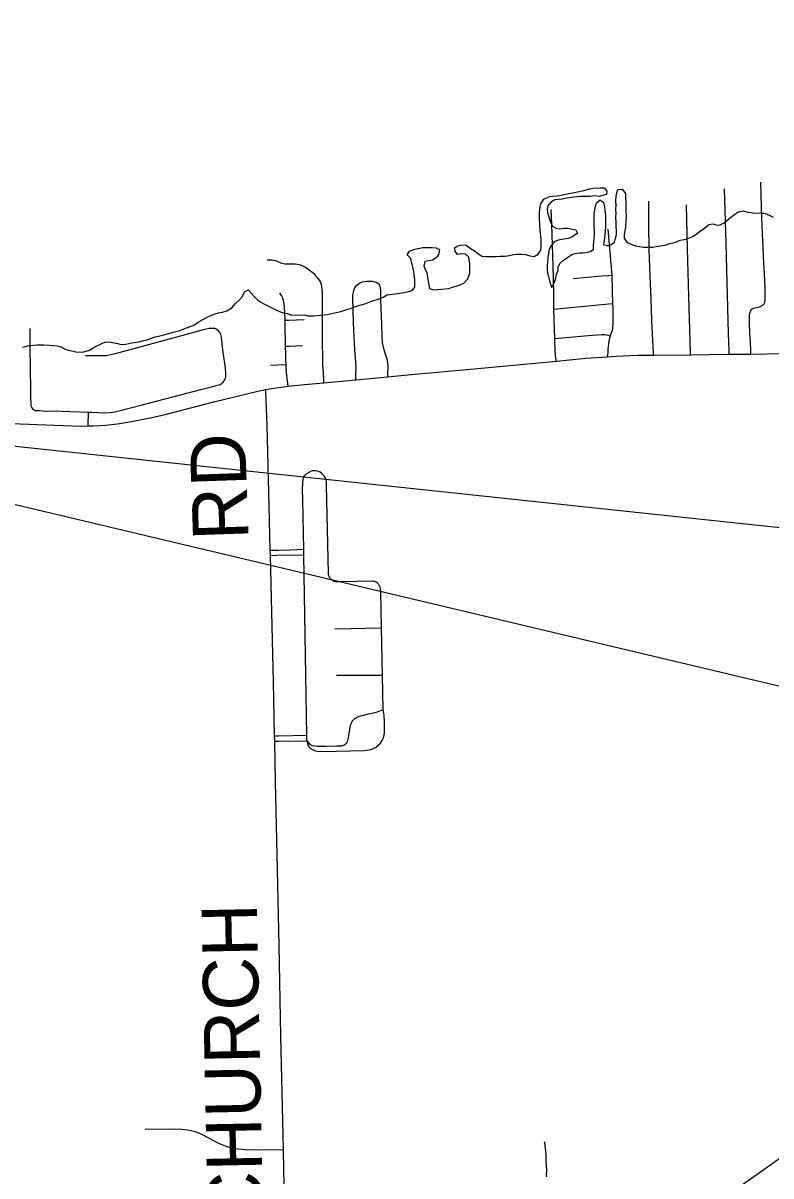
# Model space of a CAD drawing. Extents: x 63.4 to 97.4, y 0.4 to 22.4.
# Drawn here: x 69.962 to 70.728, y 16.848 to 18.029 of the extents above; entities that cross this region are included whole.
import ezdxf

# ---------------------------------------------------------------- set-up
doc = ezdxf.new("R2010")
doc.units = 0
for name, color, linetype in [('GM_X_County_Road', 7, 'Continuous'), ('GM_X_County_Road_Text', 7, 'Continuous'), ('GM_X_Minor_River', 7, 'Continuous'), ('GM_X_Rail_Line', 7, 'Continuous'), ('GM_X_State_Route', 7, 'Continuous'), ('GM_X_Township_Road', 7, 'Continuous'), ('SH_Data', 7, 'Continuous')]:
    doc.layers.add(name, color=color, linetype=linetype)

msp = doc.modelspace()

# ---------------------------------------------------------------- linework, layer by layer
at = {"layer": 'GM_X_County_Road'}
msp.add_line((70.2206, 17.2519), (70.2198, 17.2935), dxfattribs=at)
for points in [[(70.2154, 17.4839), (70.2152, 17.4891), (70.2142, 17.5343), (70.212, 17.6174), (70.2112, 17.643), (70.2106, 17.6524), (70.2104, 17.6537)], [(70.2198, 17.2935), (70.2198, 17.2953), (70.2197, 17.299), (70.2185, 17.3543), (70.2168, 17.4257), (70.2154, 17.4839)], [(70.2287, 16.8754), (70.2281, 16.9044), (70.2262, 16.9913), (70.2244, 17.0843), (70.2232, 17.1308), (70.2222, 17.1774), (70.2206, 17.2519)], [(70.2316, 16.7501), (70.2293, 16.8544), (70.2287, 16.8754)]]:
    msp.add_lwpolyline(points, dxfattribs=at)
at = {"layer": 'GM_X_Minor_River'}
for points in [[(70.3259, 17.7464), (70.3308, 17.7483), (70.335, 17.7506), (70.3433, 17.7518), (70.3479, 17.7526), (70.352, 17.753), (70.357, 17.7542), (70.3604, 17.7553), (70.3634, 17.7587), (70.3634, 17.7656), (70.363, 17.769), (70.3622, 17.7747), (70.3598, 17.785), (70.3587, 17.7884), (70.3556, 17.7918), (70.3579, 17.7956), (70.3621, 17.7971), (70.3666, 17.7983), (70.3715, 17.7991), (70.381, 17.7991), (70.3852, 17.7988), (70.3886, 17.7973), (70.3879, 17.7931), (70.386, 17.7893), (70.3815, 17.7862), (70.3773, 17.7854), (70.3735, 17.785), (70.3724, 17.7805), (70.3739, 17.777), (70.3755, 17.7732), (70.3763, 17.7687), (70.3774, 17.7626), (70.3782, 17.7573), (70.3824, 17.7558), (70.3862, 17.7562), (70.3907, 17.7566), (70.3976, 17.7574), (70.4017, 17.7585), (70.4086, 17.7605), (70.4135, 17.7628), (70.4176, 17.767), (70.4195, 17.7731), (70.4195, 17.7826), (70.4187, 17.7894), (70.4152, 17.7924), (70.4111, 17.7928), (70.4069, 17.792), (70.4046, 17.7954), (70.4038, 17.7988), (70.4072, 17.8011), (70.4114, 17.8019), (70.4159, 17.8016), (70.4198, 17.7985), (70.4255, 17.7951), (70.4289, 17.7925), (70.4323, 17.7902), (70.4365, 17.7899), (70.4468, 17.7899), (70.4506, 17.7903), (70.4555, 17.7903), (70.4604, 17.7911), (70.4642, 17.7919), (70.4676, 17.7923), (70.4733, 17.7923), (70.4767, 17.792), (70.4809, 17.7908), (70.4855, 17.7901), (70.4896, 17.7924), (70.4923, 17.7966), (70.4926, 17.8019), (70.4926, 17.8072), (70.4922, 17.811), (70.4918, 17.8164), (70.4914, 17.8224), (70.491, 17.83), (70.491, 17.8342), (70.4913, 17.8388), (70.4924, 17.8441), (70.4954, 17.8487), (70.5011, 17.8514), (70.5049, 17.8518), (70.5117, 17.8526), (70.5208, 17.8545), (70.5246, 17.8553), (70.5299, 17.8561), (70.5364, 17.8576), (70.5425, 17.8592), (70.5459, 17.8599), (70.5531, 17.8604), (70.5573, 17.8604), (70.5599, 17.857), (70.5596, 17.8535), (70.5516, 17.8516), (70.5474, 17.852), (70.5433, 17.8516), (70.5379, 17.8515), (70.5334, 17.8515), (70.5292, 17.8511), (70.5258, 17.8507), (70.5224, 17.85), (70.5186, 17.8496)], [(70.5186, 17.8496), (70.514, 17.8488), (70.5102, 17.8484), (70.5068, 17.848), (70.5027, 17.8457), (70.4996, 17.8419), (70.4989, 17.8384), (70.4993, 17.835), (70.5001, 17.8316), (70.5012, 17.8282), (70.5024, 17.8244), (70.5043, 17.821), (70.5081, 17.8191), (70.5119, 17.8184), (70.5161, 17.8191), (70.5203, 17.8192), (70.5244, 17.818), (70.5282, 17.8173), (70.5298, 17.8139), (70.5249, 17.8101), (70.5207, 17.8085), (70.5135, 17.8073), (70.5101, 17.8069), (70.5059, 17.805), (70.5033, 17.8012), (70.501, 17.7978), (70.5003, 17.7932), (70.4995, 17.789), (70.4992, 17.7841), (70.4988, 17.7803), (70.4988, 17.7769), (70.4992, 17.7731), (70.5, 17.7696), (70.5012, 17.7655), (70.5023, 17.7617), (70.5035, 17.7583), (70.5061, 17.7632), (70.5072, 17.7666), (70.5084, 17.772), (70.5099, 17.7758), (70.5102, 17.7792), (70.5117, 17.783), (70.5155, 17.7864), (70.5197, 17.7891), (70.5242, 17.7922), (70.5276, 17.793), (70.5318, 17.7937), (70.5352, 17.7938), (70.5386, 17.7942), (70.5428, 17.7953), (70.5462, 17.7972), (70.5462, 17.8014), (70.5469, 17.8083), (70.5473, 17.8121), (70.5472, 17.8162), (70.5468, 17.8197), (70.5468, 17.8299), (70.5471, 17.8341), (70.5475, 17.8379), (70.5482, 17.8417), (70.5494, 17.8451), (70.5531, 17.8482), (70.5566, 17.8452), (70.5574, 17.841), (70.5578, 17.8376), (70.5585, 17.8323), (70.5586, 17.8243), (70.5586, 17.8201), (70.5579, 17.8121), (70.5572, 17.8064), (70.5564, 17.8022), (70.561, 17.8011), (70.5644, 17.8023), (70.5678, 17.8046), (70.5689, 17.8087), (70.5697, 17.8125), (70.5696, 17.8247), (70.5692, 17.8308), (70.5695, 17.8342), (70.5691, 17.838), (70.5695, 17.843), (70.5691, 17.8468), (70.5695, 17.8517), (70.5702, 17.8551), (70.5713, 17.8585), (70.5755, 17.8589), (70.5789, 17.8544), (70.579, 17.8506), (70.5794, 17.8441), (70.5794, 17.8369), (70.5798, 17.8308), (70.5795, 17.8274), (70.5791, 17.8202), (70.5776, 17.8126), (70.5776, 17.8088), (70.5803, 17.8046), (70.5845, 17.8027), (70.5891, 17.8008), (70.5933, 17.8001), (70.5971, 17.7997), (70.6012, 17.7994)], [(70.6012, 17.7994), (70.6065, 17.7994), (70.6103, 17.8002), (70.6145, 17.801), (70.621, 17.8021), (70.6244, 17.8033), (70.6304, 17.8048), (70.635, 17.8068), (70.6411, 17.8079), (70.6445, 17.8091), (70.6479, 17.8106), (70.6513, 17.8129), (70.6558, 17.8164), (70.6596, 17.8187), (70.6645, 17.8229), (70.6687, 17.8233), (70.6721, 17.8221), (70.6759, 17.8225), (70.6801, 17.8245), (70.6869, 17.8302), (70.6907, 17.8329), (70.6944, 17.8359), (70.6994, 17.8367), (70.7032, 17.8356), (70.7093, 17.8349), (70.7176, 17.8345), (70.721, 17.8345), (70.7256, 17.8326), (70.7302, 17.8304)], [(69.962, 17.6972), (69.9685, 17.6987), (69.9768, 17.6995), (69.9833, 17.6996), (69.989, 17.6992), (69.9928, 17.6989), (69.997, 17.6985), (70.0011, 17.6974), (70.0046, 17.6955), (70.0084, 17.694), (70.0133, 17.6929), (70.0175, 17.6921), (70.0243, 17.6922), (70.03, 17.6941), (70.0357, 17.6975), (70.0429, 17.701), (70.0467, 17.7025), (70.052, 17.7022), (70.0573, 17.7011), (70.0626, 17.6999), (70.0672, 17.7003), (70.0736, 17.7015), (70.0808, 17.7027), (70.0842, 17.7035), (70.0888, 17.7046), (70.0975, 17.7077), (70.1009, 17.7085), (70.1062, 17.7096), (70.11, 17.7108), (70.1157, 17.7124), (70.1225, 17.7143), (70.1294, 17.717), (70.1362, 17.7193), (70.143, 17.7239), (70.1521, 17.7285), (70.1589, 17.7312), (70.1623, 17.7323), (70.1665, 17.7331), (70.1707, 17.7343), (70.1759, 17.7373), (70.1797, 17.7419), (70.1839, 17.7457), (70.1869, 17.7492), (70.1888, 17.7538), (70.1926, 17.7557), (70.1987, 17.7492), (70.2036, 17.7443), (70.2101, 17.7409), (70.2135, 17.739), (70.2196, 17.736), (70.2246, 17.7338), (70.2284, 17.7323), (70.2329, 17.7315), (70.2375, 17.73), (70.2504, 17.7301), (70.2538, 17.7293), (70.2599, 17.7294), (70.2671, 17.7298), (70.2739, 17.7306), (70.2796, 17.7321), (70.2876, 17.7337), (70.2937, 17.7356), (70.2982, 17.7372), (70.3046, 17.7395), (70.3122, 17.7414), (70.3194, 17.7441), (70.3259, 17.7464)], [(70.4986, 16.8474), (70.4982, 16.8497), (70.4983, 16.8546), (70.4977, 16.8638), (70.4978, 16.8695), (70.4974, 16.874), (70.4971, 16.8759), (70.4968, 16.8786), (70.4968, 16.8797), (70.4964, 16.882), (70.4961, 16.8832)]]:
    msp.add_lwpolyline(points, dxfattribs=at)
at = {"layer": 'GM_X_Rail_Line'}
msp.add_lwpolyline([(65.5072, 16.0914), (66.1191, 16.083), (66.4239, 16.0787), (66.8313, 16.0688), (67.543, 16.0626), (67.9702, 16.0577), (68.6101, 16.2463), (69.1053, 16.3972), (70.1929, 16.7393), (70.2646, 16.7591), (70.3642, 16.7634), (70.5898, 16.7764), (70.6857, 16.8302), (70.7827, 16.8988), (71.2174, 17.2501), (71.5086, 17.4876), (71.6576, 17.6039), (72.13, 17.975), (72.3072, 18.116)], dxfattribs=at)
at = {"layer": 'GM_X_State_Route'}
msp.add_lwpolyline([(69.9504, 17.6191), (70.0032, 17.6168), (70.0218, 17.6163), (70.0287, 17.6164), (70.0342, 17.6165), (70.0466, 17.6173), (70.0589, 17.6187), (70.0712, 17.6206), (70.0925, 17.6248), (70.1076, 17.6283), (70.1588, 17.6415), (70.2011, 17.6517), (70.2104, 17.6537), (70.2164, 17.6548), (70.2288, 17.6566), (70.2335, 17.6571), (70.2504, 17.6589), (70.2702, 17.6607), (70.3028, 17.6638), (70.3352, 17.6668), (70.3557, 17.6688), (70.4239, 17.675), (70.5082, 17.6829), (70.5385, 17.6858), (70.5607, 17.6874), (70.5695, 17.688), (70.5913, 17.6888), (70.608, 17.689), (70.6456, 17.6894), (70.6852, 17.6899), (70.7073, 17.6901), (70.7406, 17.6905)], dxfattribs=at)
at = {"layer": 'GM_X_Township_Road'}
for p, q in [((70.2154, 17.6788), (70.2315, 17.6795)), ((70.2496, 17.4845), (70.2495, 17.4901)), ((70.2526, 17.2997), (70.2496, 17.4845)), ((70.2814, 17.4085), (70.3292, 17.4098)), ((70.3302, 17.361), (70.3292, 17.4098)), ((70.283, 17.361), (70.3302, 17.361)), ((70.331, 17.326), (70.3302, 17.361)), ((70.2527, 17.294), (70.2526, 17.2997))]:
    msp.add_line(p, q, dxfattribs=at)
for points in [[(70.6852, 17.6899), (70.6851, 17.6935), (70.6844, 17.7113), (70.6832, 17.7637), (70.682, 17.8037), (70.6804, 17.8594)], [(70.7073, 17.6901), (70.7072, 17.6935), (70.707, 17.7022), (70.7064, 17.7117), (70.7061, 17.7209), (70.706, 17.7285), (70.7061, 17.7303), (70.7065, 17.7321), (70.7069, 17.7335), (70.7075, 17.7348), (70.7085, 17.7361), (70.7097, 17.7367), (70.7114, 17.7374), (70.7133, 17.7377), (70.7161, 17.7385), (70.7175, 17.739), (70.7186, 17.7396), (70.7194, 17.7402), (70.7201, 17.7407), (70.7206, 17.7412), (70.721, 17.7418), (70.7214, 17.7426), (70.7217, 17.7435), (70.7219, 17.7443), (70.7221, 17.7452), (70.7222, 17.7459), (70.7222, 17.7468), (70.7222, 17.7483), (70.7222, 17.7514), (70.7219, 17.7577), (70.7213, 17.7725), (70.7205, 17.7827), (70.7186, 17.8293), (70.7178, 17.8526), (70.7176, 17.8661)], [(70.608, 17.689), (70.6078, 17.6916), (70.6065, 17.7106), (70.6061, 17.7246), (70.6053, 17.7465), (70.6043, 17.7703), (70.6034, 17.7968), (70.6028, 17.8232), (70.6028, 17.8466)], [(70.5055, 17.7361), (70.5055, 17.7479), (70.5055, 17.7535), (70.5048, 17.7805), (70.5035, 17.8227), (70.5028, 17.8382)], [(70.6456, 17.6894), (70.6455, 17.692), (70.6438, 17.749), (70.6426, 17.7981), (70.6415, 17.8431)], [(70.5653, 17.771), (70.5649, 17.7745), (70.5633, 17.7944), (70.5613, 17.8179)], [(70.2702, 17.6607), (70.27, 17.6643), (70.2693, 17.676), (70.2692, 17.6783), (70.2687, 17.7097), (70.2686, 17.7406), (70.2687, 17.7533), (70.2684, 17.757), (70.2682, 17.7593), (70.2677, 17.7611), (70.2671, 17.7632), (70.2662, 17.7647), (70.2645, 17.7673), (70.2626, 17.7696), (70.2604, 17.7718), (70.2568, 17.7748), (70.2534, 17.7775), (70.2506, 17.7792), (70.2487, 17.7802), (70.2466, 17.781), (70.2447, 17.7815), (70.2429, 17.7818), (70.2407, 17.7821), (70.2372, 17.7822), (70.2314, 17.782), (70.2301, 17.7822), (70.2288, 17.7825), (70.2275, 17.7828), (70.2263, 17.7832), (70.2233, 17.7847), (70.222, 17.7852), (70.2208, 17.7856), (70.2193, 17.7859), (70.2171, 17.7861), (70.2122, 17.7862)], [(70.3028, 17.6638), (70.3029, 17.668), (70.3031, 17.6764), (70.3029, 17.682), (70.3017, 17.6944), (70.3009, 17.7143), (70.3001, 17.7329), (70.2999, 17.749), (70.3001, 17.7524), (70.3007, 17.7552), (70.3015, 17.7573), (70.3027, 17.7591), (70.304, 17.7607), (70.3057, 17.7621), (70.3078, 17.7633), (70.3098, 17.764), (70.312, 17.7645), (70.3145, 17.7648), (70.3173, 17.7648), (70.3199, 17.7647), (70.3222, 17.7642), (70.3238, 17.7636), (70.3254, 17.7627), (70.3264, 17.7618), (70.3271, 17.7606), (70.3276, 17.7592), (70.3278, 17.7578), (70.328, 17.7547), (70.3281, 17.7514), (70.3283, 17.7454), (70.329, 17.7205), (70.3294, 17.7081), (70.33, 17.702), (70.3305, 17.6989), (70.3312, 17.6959), (70.334, 17.6871), (70.3348, 17.6841), (70.3352, 17.6806), (70.3355, 17.6771), (70.3353, 17.6709), (70.3352, 17.6668)], [(70.5254, 17.7675), (70.5549, 17.7703), (70.5616, 17.7707), (70.5653, 17.771)], [(70.5662, 17.7418), (70.5658, 17.7549), (70.5653, 17.771)], [(70.2304, 17.7248), (70.2301, 17.733), (70.2294, 17.7415), (70.2289, 17.7449), (70.2282, 17.7474), (70.2269, 17.7499), (70.225, 17.7523)], [(70.5055, 17.7361), (70.5616, 17.7414), (70.5662, 17.7418)], [(70.5635, 17.7089), (70.5644, 17.7112), (70.5651, 17.7127), (70.5656, 17.7147), (70.5659, 17.7162), (70.5662, 17.718), (70.5663, 17.7204), (70.5663, 17.7245), (70.5664, 17.7359), (70.5662, 17.7418)], [(70.5066, 17.7061), (70.5059, 17.7255), (70.5055, 17.7361)], [(69.9692, 17.7161), (69.9691, 17.7094), (69.9691, 17.697), (69.9698, 17.6535), (69.9699, 17.644), (69.97, 17.6408), (69.9701, 17.6376), (69.9704, 17.6362), (69.971, 17.6349), (69.972, 17.6337), (69.9731, 17.6329), (69.9744, 17.6324), (69.9761, 17.6323), (69.9794, 17.6321), (69.9826, 17.632), (70.0015, 17.6315), (70.0291, 17.6305)], [(70.0291, 17.6305), (70.0325, 17.6304), (70.0449, 17.63), (70.0511, 17.6302), (70.0541, 17.6305), (70.0602, 17.6318), (70.0842, 17.6381), (70.1233, 17.6482), (70.1443, 17.6538), (70.1563, 17.6569), (70.1598, 17.6577), (70.1625, 17.6584), (70.1639, 17.659), (70.1653, 17.6598), (70.1664, 17.6608), (70.1673, 17.6617), (70.1682, 17.6629), (70.1688, 17.6641), (70.1693, 17.6655), (70.1696, 17.6668), (70.1697, 17.668), (70.1698, 17.6697), (70.1693, 17.676), (70.1671, 17.6916), (70.1658, 17.704), (70.1652, 17.7073), (70.1645, 17.7102), (70.1638, 17.7117), (70.163, 17.7129), (70.1621, 17.7139), (70.161, 17.7148), (70.1597, 17.7156), (70.1585, 17.7161), (70.1569, 17.7163), (70.1556, 17.7164), (70.1541, 17.7164), (70.1526, 17.7162), (70.1464, 17.7148), (70.1194, 17.7073), (70.0565, 17.6903), (70.0504, 17.6889), (70.0474, 17.6884), (70.0443, 17.6881), (70.0381, 17.6882), (70.0262, 17.6884)], [(70.2304, 17.7248), (70.2342, 17.7249), (70.2501, 17.7254)], [(70.2309, 17.698), (70.2308, 17.7017), (70.2306, 17.7175), (70.2304, 17.7248)], [(70.5066, 17.7061), (70.5407, 17.7091), (70.5548, 17.7102), (70.5582, 17.7102), (70.5635, 17.7089)], [(70.5082, 17.6829), (70.5078, 17.686), (70.5069, 17.6935), (70.5067, 17.7048), (70.5066, 17.7061)], [(70.5607, 17.6874), (70.5611, 17.6914), (70.5613, 17.6952), (70.5619, 17.7007), (70.5623, 17.7031), (70.5627, 17.7054), (70.5635, 17.7089)], [(70.2309, 17.698), (70.2347, 17.6981), (70.2484, 17.6987)], [(70.2315, 17.6795), (70.2312, 17.6845), (70.2312, 17.69), (70.2309, 17.698)], [(70.2335, 17.6571), (70.2324, 17.6649), (70.2319, 17.6716), (70.2315, 17.6781), (70.2315, 17.6795)], [(70.0287, 17.6164), (70.0288, 17.6192), (70.029, 17.6281), (70.0291, 17.6305)], [(70.2495, 17.4901), (70.2487, 17.5401), (70.2484, 17.5523), (70.2485, 17.557), (70.2485, 17.5582), (70.2485, 17.5591), (70.2488, 17.5605), (70.2489, 17.5613), (70.2491, 17.5621), (70.2496, 17.5637), (70.2501, 17.5647), (70.2508, 17.5656), (70.2514, 17.5664), (70.252, 17.567), (70.2527, 17.5677), (70.2534, 17.5682), (70.2544, 17.5689), (70.2559, 17.5696), (70.2573, 17.5702)], [(70.3292, 17.4098), (70.3285, 17.4466), (70.3282, 17.4498), (70.3279, 17.4512), (70.3273, 17.4527), (70.3266, 17.4538), (70.326, 17.4545), (70.3255, 17.4552), (70.3246, 17.4558), (70.3237, 17.4564), (70.3229, 17.4568), (70.322, 17.457), (70.321, 17.4572), (70.3196, 17.4573), (70.2886, 17.4567), (70.2823, 17.4569), (70.2814, 17.4571), (70.2799, 17.4576), (70.2794, 17.4578), (70.2785, 17.4583), (70.2775, 17.4591), (70.277, 17.4597), (70.2765, 17.4604), (70.276, 17.4611), (70.2755, 17.4623), (70.2752, 17.4631), (70.275, 17.4642), (70.2748, 17.4653), (70.273, 17.5559), (70.2728, 17.559), (70.2724, 17.5609), (70.2717, 17.5631), (70.2708, 17.5648), (70.2699, 17.5661), (70.2688, 17.5672), (70.2677, 17.5682), (70.2663, 17.569), (70.2654, 17.5695), (70.2646, 17.5698), (70.2634, 17.5702), (70.2619, 17.5704), (70.2605, 17.5705), (70.2596, 17.5704), (70.2582, 17.5703), (70.2573, 17.5702)], [(70.2152, 17.4891), (70.2233, 17.4893), (70.2354, 17.4896), (70.2495, 17.4901)], [(70.2154, 17.4839), (70.222, 17.484), (70.2496, 17.4845)], [(70.2527, 17.294), (70.2542, 17.2886), (70.2552, 17.2874), (70.2563, 17.2861), (70.2578, 17.2852), (70.2591, 17.2845), (70.2605, 17.284), (70.2633, 17.2834), (70.2681, 17.2831), (70.3117, 17.284), (70.3144, 17.2842), (70.3164, 17.2845), (70.3179, 17.2849), (70.3194, 17.2853), (70.3208, 17.2859), (70.323, 17.287), (70.3246, 17.2882), (70.3259, 17.2894), (70.3281, 17.2916), (70.3299, 17.2942), (70.3312, 17.297), (70.3317, 17.2984), (70.332, 17.2999), (70.3322, 17.3017), (70.3323, 17.3037), (70.3324, 17.3061), (70.3323, 17.3133), (70.3318, 17.3202), (70.331, 17.326)], [(70.2527, 17.294), (70.2552, 17.291), (70.2563, 17.2901), (70.2574, 17.2895), (70.2583, 17.2891), (70.2606, 17.2887), (70.2634, 17.2885), (70.2657, 17.2884), (70.2719, 17.2884), (70.2832, 17.2886), (70.2867, 17.2888), (70.2881, 17.2889), (70.2894, 17.2891), (70.2907, 17.2895), (70.2921, 17.2903), (70.2928, 17.2909), (70.2934, 17.2915), (70.2943, 17.293), (70.2947, 17.2941), (70.2951, 17.2955), (70.2953, 17.2969), (70.2956, 17.2996), (70.2963, 17.3036), (70.2971, 17.308), (70.2974, 17.3094), (70.2979, 17.311), (70.2984, 17.3124), (70.2992, 17.3136), (70.2998, 17.3146), (70.3005, 17.3155), (70.3012, 17.3161), (70.3018, 17.3167), (70.3034, 17.3179), (70.3063, 17.3192), (70.3106, 17.3203), (70.3158, 17.3215), (70.3239, 17.3234), (70.3273, 17.3245), (70.331, 17.326)], [(70.2197, 17.299), (70.2236, 17.2991), (70.2526, 17.2997)], [(70.2198, 17.2935), (70.2233, 17.2935), (70.2527, 17.294)], [(70.0873, 16.896), (70.1153, 16.8963), (70.1247, 16.896), (70.1309, 16.8954), (70.134, 16.8948), (70.137, 16.894), (70.1399, 16.893), (70.1456, 16.8906), (70.1622, 16.8818), (70.1673, 16.8796), (70.1709, 16.8782), (70.1742, 16.8772), (70.1782, 16.8764), (70.1832, 16.8758), (70.1893, 16.8754), (70.2017, 16.875), (70.2287, 16.8754)]]:
    msp.add_lwpolyline(points, dxfattribs=at)
at = {"layer": 'SH_Data'}
msp.add_lwpolyline([(69.5016, 17.6434), (73.2341, 16.7563), (73.2341, 17.2463)], close=True, dxfattribs=at)

# ---------------------------------------------------------------- texts
at = {"layer": 'GM_X_County_Road_Text'}
for s, rotation, p in [('RD', 91.9772, (70.1931, 17.5002)), ('CHURCH', 91.1467, (70.2081, 16.7986))]:
    msp.add_text(s, height=0.05682, rotation=rotation, dxfattribs=at).set_placement(p)

doc.saveas('drawing.dxf')
